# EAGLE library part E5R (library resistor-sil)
SIL RESISTOR
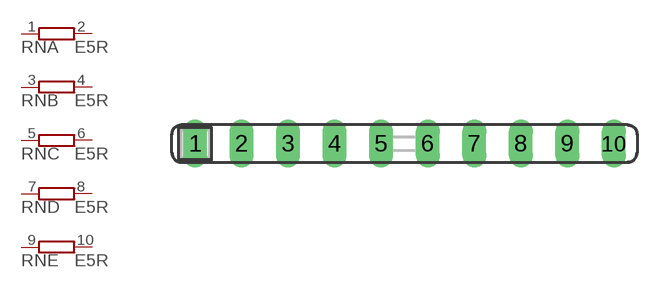
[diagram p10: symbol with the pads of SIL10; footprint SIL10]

Designator prefix RN; gates A=RNV B=RNV C=RNV D=RNV E=RNV

## E5R (OC_FARNELL: unknown; OC_NEWARK: unknown)  [SIL10]
1  A:1  pas
2  A:2  pas
3  B:1  pas
4  B:2  pas
5  C:1  pas
6  C:2  pas
7  D:1  pas
8  D:2  pas
9  E:1  pas
10  E:2  pas

## Footprint SIL10 (pad centres in mm)
Single In Line
drill 0.813 long: 1 -11.43,0; 2 -8.89,0; 3 -6.35,0; 4 -3.81,0; 5 -1.27,0; 6 1.27,0; 7 3.81,0; 8 6.35,0; 9 8.89,0; 10 11.43,0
